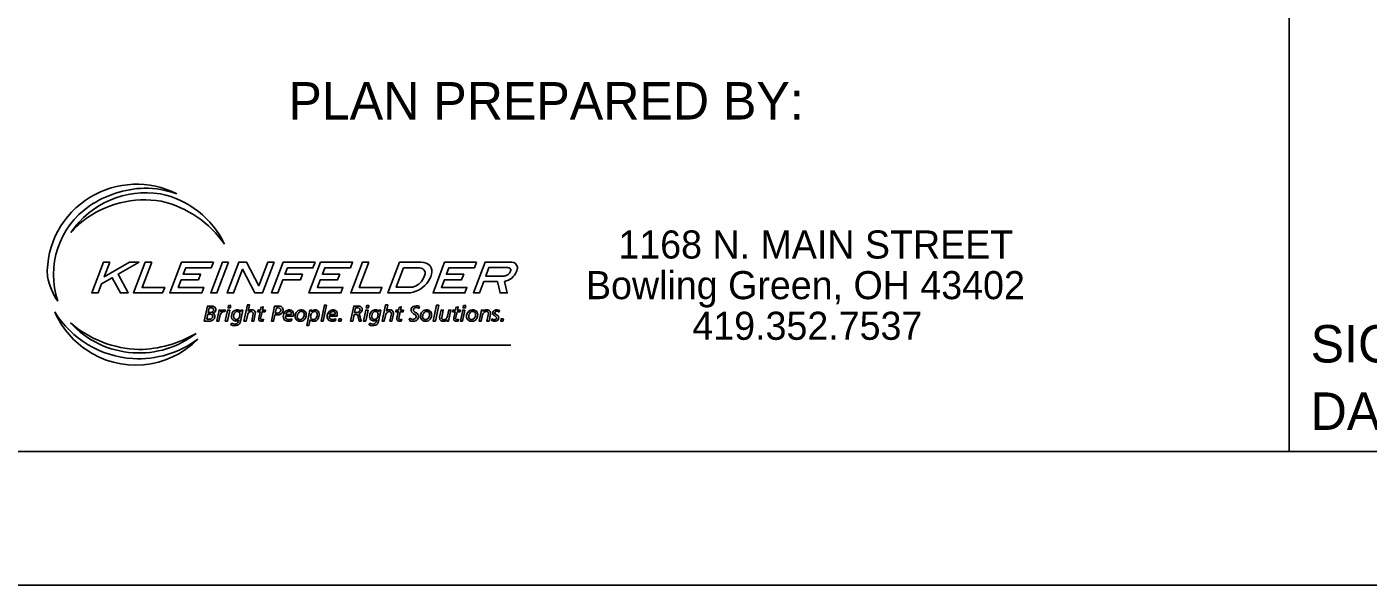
# Model space of a CAD drawing. Extents: x -107 to 120, y -81 to 213.
# Drawn here: x 6.52 to 11.53, y 1.57 to 3.66 of the extents above; entities that cross this region are included whole.
import ezdxf

# ---------------------------------------------------------------- set-up
doc = ezdxf.new("R2010")
doc.units = 0
for name, color, linetype in [('SH_Border', 7, 'Continuous'), ('SH_Cut_Line', 7, 'Continuous'), ('SH_Data', 7, 'Continuous'), ('SH_Text', 7, 'Continuous')]:
    doc.layers.add(name, color=color, linetype=linetype)

msp = doc.modelspace()

# ---------------------------------------------------------------- linework, layer by layer
at = {"layer": 'SH_Border'}
msp.add_lwpolyline([(5.389, 23.0682), (37.389, 23.0682), (37.389, 2.0682), (5.389, 2.0682)], close=True, dxfattribs=at)
at = {"layer": 'SH_Cut_Line'}
msp.add_lwpolyline([(3.889, 1.5682), (37.889, 1.5682), (37.889, 23.5682), (3.889, 23.5682)], close=True, dxfattribs=at)
at = {"layer": 'SH_Data'}
msp.add_line((11.239, 2.0682), (11.239, 5.3182), dxfattribs=at)
at = {"layer": 'SH_Text'}
for p, q in [((8.2506, 2.7552), (8.3209, 2.7553)), ((7.9891, 2.6024), (7.9914, 2.6098)), ((7.2066, 2.5621), (7.1966, 2.5621)), ((7.2109, 2.5874), (7.2019, 2.5874)), ((7.3223, 2.5538), (7.3313, 2.5968)), ((7.4071, 2.5556), (7.4086, 2.5624)), ((7.4511, 2.5783), (7.4613, 2.5783)), ((7.4599, 2.5851), (7.4525, 2.5851)), ((7.5122, 2.5802), (7.4918, 2.5802)), ((7.5132, 2.5565), (7.5146, 2.5636)), ((7.6759, 2.5802), (7.6554, 2.5802)), ((7.6769, 2.5565), (7.6782, 2.5636)), ((7.7589, 2.5876), (7.7488, 2.5876)), ((7.8382, 2.5538), (7.8472, 2.5968)), ((7.923, 2.5556), (7.9245, 2.5624)), ((7.9547, 2.5661), (7.9522, 2.5583)), ((8.1261, 2.5648), (8.1315, 2.5903)), ((8.1353, 2.5556), (8.1368, 2.5624)), ((8.2612, 2.5635), (8.2598, 2.5571)), ((8.2883, 2.5886), (8.2903, 2.5952)), ((7.2887, 2.5481), (7.2867, 2.5411)), ((7.8046, 2.5481), (7.8026, 2.5411))]:
    msp.add_line(p, q, dxfattribs=at)
for points in [[(6.9446, 2.7755), (6.9085, 2.7755), (6.8141, 2.7213), (6.8346, 2.7755), (6.8107, 2.7755), (6.7672, 2.6606), (6.7911, 2.6606), (6.8041, 2.6948), (6.8438, 2.7176), (6.874, 2.6606), (6.9027, 2.6606), (6.8657, 2.7302), (6.9446, 2.7755)], [(6.9909, 2.7755), (6.9668, 2.7755), (6.9233, 2.6606), (7.0319, 2.6606), (7.0399, 2.6811), (6.9552, 2.6811), (6.9909, 2.7755)], [(7.2212, 2.7755), (7.1022, 2.7755), (7.0587, 2.6606), (7.1777, 2.6606), (7.1856, 2.6813), (7.0902, 2.6813), (7.1011, 2.71), (7.1656, 2.71), (7.1735, 2.7307), (7.1089, 2.7307), (7.1179, 2.7545), (7.2133, 2.7545), (7.2212, 2.7755)], [(7.2782, 2.7755), (7.2552, 2.7755), (7.2118, 2.6606), (7.2347, 2.6606), (7.2782, 2.7755)], [(7.3446, 2.7755), (7.3163, 2.7755), (7.2728, 2.6606), (7.2965, 2.6606), (7.33, 2.749), (7.3765, 2.6606), (7.4047, 2.6606), (7.4482, 2.7755), (7.4242, 2.7755), (7.3909, 2.6876), (7.3446, 2.7755)], [(7.5539, 2.7307), (7.4888, 2.7307), (7.4977, 2.7543), (7.5933, 2.7543), (7.6014, 2.7755), (7.4825, 2.7755), (7.439, 2.6606), (7.4623, 2.6606), (7.4809, 2.7099), (7.5461, 2.7099), (7.5539, 2.7307)], [(7.6931, 2.7307), (7.6286, 2.7307), (7.6376, 2.7545), (7.7329, 2.7545), (7.7409, 2.7755), (7.6219, 2.7755), (7.5784, 2.6606), (7.6974, 2.6606), (7.7052, 2.6813), (7.6099, 2.6813), (7.6207, 2.71), (7.6853, 2.71), (7.6931, 2.7307)], [(7.802, 2.7755), (7.7778, 2.7755), (7.7343, 2.6606), (7.843, 2.6606), (7.851, 2.6811), (7.7662, 2.6811), (7.802, 2.7755)], [(7.9978, 2.7755), (7.9168, 2.7755), (7.8733, 2.6606), (7.9465, 2.6606)], [(8.204, 2.7755), (8.085, 2.7755), (8.0415, 2.6606), (8.1605, 2.6606), (8.1684, 2.6813), (8.073, 2.6813), (8.0839, 2.71), (8.1484, 2.71), (8.1563, 2.7307), (8.0917, 2.7307), (8.1007, 2.7545), (8.1961, 2.7545), (8.204, 2.7755)], [(8.336, 2.7755), (8.2363, 2.7755), (8.1928, 2.6606), (8.2148, 2.6606), (8.2308, 2.7029), (8.282, 2.7029), (8.2921, 2.6606), (8.3185, 2.6606), (8.3088, 2.7039)], [(8.3068, 2.7237), (8.2387, 2.7237), (8.2506, 2.7552)], [(7.9556, 2.6817), (7.9042, 2.6817), (7.9317, 2.7544), (7.9918, 2.7544)], [(7.2171, 2.6115), (7.1988, 2.6115), (7.187, 2.5556), (7.21, 2.5556)], [(7.2019, 2.5874), (7.2057, 2.605), (7.2137, 2.605)], [(7.2864, 2.6132), (7.2782, 2.6132), (7.2763, 2.6046), (7.2845, 2.6046), (7.2864, 2.6132)], [(7.3515, 2.5919), (7.3566, 2.6156), (7.3484, 2.6156), (7.3356, 2.5556), (7.3438, 2.5556), (7.3483, 2.5767)], [(7.4159, 2.5968), (7.4047, 2.5968), (7.4072, 2.6088), (7.399, 2.6056), (7.3971, 2.5968), (7.388, 2.5968), (7.3867, 2.5903), (7.3957, 2.5903), (7.3908, 2.5657)], [(7.4675, 2.6115), (7.4499, 2.6115), (7.4381, 2.5556), (7.4463, 2.5556), (7.4511, 2.5783)], [(7.6443, 2.6154), (7.6361, 2.6154), (7.6236, 2.5556), (7.6318, 2.5556), (7.6443, 2.6154)], [(7.7652, 2.6115), (7.7456, 2.6115), (7.7338, 2.5556), (7.742, 2.5556), (7.7473, 2.5806), (7.7544, 2.5806)], [(7.8023, 2.6132), (7.7941, 2.6132), (7.7922, 2.6046), (7.8004, 2.6046), (7.8023, 2.6132)], [(7.8674, 2.5919), (7.8725, 2.6156), (7.8643, 2.6156), (7.8515, 2.5556), (7.8597, 2.5556), (7.8642, 2.5767)], [(7.9318, 2.5968), (7.9206, 2.5968), (7.9231, 2.6088), (7.9149, 2.6056), (7.913, 2.5968), (7.9039, 2.5968), (7.9026, 2.5903), (7.9116, 2.5903), (7.9067, 2.5657)], [(8.0629, 2.6154), (8.0546, 2.6154), (8.0421, 2.5556), (8.0503, 2.5556), (8.0629, 2.6154)], [(8.1315, 2.5903), (8.1427, 2.5903), (8.144, 2.5968), (8.1328, 2.5968), (8.1354, 2.6088), (8.1271, 2.6056), (8.1253, 2.5968), (8.1162, 2.5968), (8.1148, 2.5903), (8.1239, 2.5903), (8.119, 2.5657)], [(8.164, 2.6132), (8.1558, 2.6132), (8.154, 2.6046), (8.1622, 2.6046), (8.164, 2.6132)], [(7.1966, 2.5621), (7.2006, 2.581), (7.2093, 2.581)], [(7.2494, 2.5905), (7.2507, 2.5968), (7.2428, 2.5968), (7.2341, 2.5556), (7.2419, 2.5556), (7.247, 2.5792)], [(7.2643, 2.5904), (7.2659, 2.5968), (7.2589, 2.5968)], [(7.2829, 2.5968), (7.2747, 2.5968), (7.2659, 2.5556), (7.2742, 2.5556), (7.2829, 2.5968)], [(7.3313, 2.5968), (7.3239, 2.5968), (7.3225, 2.5901)], [(7.3701, 2.5821), (7.3646, 2.5556), (7.3723, 2.5556), (7.3779, 2.5821)], [(7.3979, 2.5648), (7.4033, 2.5903), (7.4145, 2.5903), (7.4159, 2.5968)], [(7.4525, 2.5851), (7.4566, 2.6045), (7.4638, 2.6045)], [(7.4905, 2.5701), (7.4908, 2.5742), (7.5196, 2.5742), (7.5202, 2.577)], [(7.5876, 2.5905), (7.5887, 2.5968), (7.582, 2.5968), (7.5698, 2.5394), (7.578, 2.5394), (7.5827, 2.5614)], [(7.6541, 2.5701), (7.6544, 2.5742), (7.6832, 2.5742), (7.6838, 2.577)], [(7.6993, 2.5642), (7.6911, 2.5642), (7.6892, 2.5556), (7.6975, 2.5556), (7.6993, 2.5642)], [(7.7488, 2.5876), (7.7524, 2.6046), (7.761, 2.6046)], [(7.7602, 2.5764), (7.7652, 2.5556), (7.7736, 2.5556), (7.767, 2.5793)], [(7.7988, 2.5968), (7.7906, 2.5968), (7.7818, 2.5556), (7.7901, 2.5556), (7.7988, 2.5968)], [(7.8472, 2.5968), (7.8398, 2.5968), (7.8384, 2.5901)], [(7.886, 2.5821), (7.8805, 2.5556), (7.8882, 2.5556), (7.8938, 2.5821)], [(7.9138, 2.5648), (7.9192, 2.5903), (7.9304, 2.5903), (7.9318, 2.5968)], [(8.0739, 2.5688), (8.0798, 2.5968), (8.0716, 2.5968), (8.0663, 2.5716)], [(8.0937, 2.5616), (8.0926, 2.5556), (8.0999, 2.5556), (8.1087, 2.5968), (8.1005, 2.5968), (8.0955, 2.5733)], [(8.1605, 2.5968), (8.1523, 2.5968), (8.1436, 2.5556), (8.1518, 2.5556), (8.1605, 2.5968)], [(8.2286, 2.5908), (8.2298, 2.5968), (8.2224, 2.5968), (8.2137, 2.5556), (8.2219, 2.5556), (8.2268, 2.5791)], [(8.2484, 2.5836), (8.2425, 2.5556), (8.2507, 2.5556), (8.2561, 2.5808)], [(8.3044, 2.5642), (8.2962, 2.5642), (8.2944, 2.5556), (8.3026, 2.5556), (8.3044, 2.5642)], [(8.3326, 2.4657), (7.3164, 2.4657)]]:
    msp.add_lwpolyline(points, dxfattribs=at)
for centre, radius, start, end in [((6.9345, 2.7342), 0.3328, 63.0899, 121.3353), ((6.931, 2.7354), 0.3299, 120.9374, 182.3516), ((6.9691, 2.6985), 0.3369, 80.6744, 146.0558), ((6.9642, 2.6353), 0.3734, 80.3407, 127.7725), ((6.9778, 2.6584), 0.3942, 92.1375, 123.7556), ((6.9625, 2.6895), 0.3628, 70.2384, 89.8908), ((6.9553, 2.6981), 0.3398, 25.1143, 78.3777), ((6.937, 2.7291), 0.3127, 124.7279, 198.5434), ((6.9379, 2.6194), 0.3942, 34.4536, 76.9641), ((6.9248, 2.6861), 0.3091, 127.7725, 139.547), ((7.9973, 2.7274), 0.0481, 45.8191, 89.4263), ((8.0018, 2.7409), 0.0358, 343.1779, 35.9306), ((8.3215, 2.7436), 0.0116, 30.9282, 92.8587), ((8.3343, 2.752), 0.0235, 15.8602, 85.9527), ((8.3211, 2.7563), 0.0359, 333.9111, 3.4134), ((6.8465, 2.7714), 0.25, 191.4129, 214.5262), ((7.9503, 2.7431), 0.0624, 294.8644, 346.4065), ((7.948, 2.7535), 0.0911, 295.2799, 345.3517), ((7.9919, 2.734), 0.0203, 22.5545, 90.292), ((7.9929, 2.7347), 0.0192, 340.7496, 21.8258), ((8.3052, 2.7515), 0.0278, 273.188, 339.9483), ((8.2984, 2.762), 0.059, 280.1322, 338.6534), ((8.3193, 2.746), 0.0128, 341.295, 16.2465), ((7.9458, 2.7457), 0.0851, 270.5101, 298.8607), ((7.9564, 2.7275), 0.0458, 268.9317, 296.1463), ((7.2142, 2.5966), 0.00845, 14.5669, 93.2204), ((7.2164, 2.5967), 0.0148, 28.8217, 87.6001), ((7.4669, 2.5957), 0.0158, 36.8786, 87.6793), ((7.4634, 2.5965), 0.0183, 337.3357, 28.1453), ((7.7638, 2.5973), 0.0143, 24.3537, 84.3612), ((7.9751, 2.5961), 0.0157, 117.7495, 163.8409), ((7.9808, 2.5765), 0.0359, 92.7278, 111.3007), ((7.979, 2.5934), 0.0124, 85.3728, 140.5265), ((7.9803, 2.5878), 0.0246, 63.0923, 92.7278), ((7.98, 2.5913), 0.0144, 50.4782, 89.939), ((6.933, 2.7216), 0.3314, 203.3176, 235.0704), ((6.944, 2.7846), 0.3703, 211.6203, 266.4398), ((6.933, 2.7216), 0.3314, 203.3176, 235.0704), ((6.944, 2.7846), 0.3703, 211.6203, 266.4398), ((7.2062, 2.5756), 0.0135, 271.8674, 330.8259), ((7.211, 2.573), 0.00818, 23.2405, 101.7775), ((7.2082, 2.5763), 0.0207, 274.8421, 325.7541), ((7.2099, 2.6028), 0.0155, 273.7446, 308.6277), ((7.2112, 2.5731), 0.00788, 328.3862, 23.2405), ((7.2157, 2.6042), 0.0195, 278.6642, 301.5112), ((7.2144, 2.5727), 0.0129, 9.5096, 70.7154), ((7.2141, 2.5971), 0.0084, 310.2808, 10.5581), ((7.2144, 2.5718), 0.0131, 326.795, 13.6323), ((7.2138, 2.5987), 0.0165, 317.423, 18.0377), ((7.2653, 2.5728), 0.0194, 115.713, 160.7037), ((7.2609, 2.5833), 0.0136, 98.2387, 147.9511), ((7.2607, 2.5811), 0.00995, 68.8231, 112.4085), ((7.3156, 2.5736), 0.0268, 153.1201, 200.541), ((7.3046, 2.5715), 0.0158, 207.2493, 259.812), ((7.3096, 2.5781), 0.0195, 76.4234, 156.8498), ((7.3198, 2.573), 0.0229, 134.9845, 190.2941), ((7.3059, 2.5704), 0.00874, 190.0175, 280.7991), ((7.3052, 2.5708), 0.0154, 257.3096, 315.7047), ((7.3103, 2.5814), 0.0102, 66.145, 130.58), ((7.3065, 2.5742), 0.0125, 274.6127, 341.2311), ((7.2981, 2.5606), 0.0181, 322.9431, 358.3704), ((7.312, 2.5859), 0.0113, 21.6426, 78.888), ((7.3097, 2.5814), 0.0105, 3.2154, 63.4686), ((7.2978, 2.5796), 0.0226, 335.4895, 6.081), ((7.3682, 2.573), 0.0202, 120.678, 169.5619), ((7.3622, 2.5847), 0.0129, 95.2859, 145.9293), ((7.362, 2.5834), 0.00818, 46.5529, 120.7681), ((7.3639, 2.5808), 0.017, 55.2436, 99.7855), ((7.3628, 2.5836), 0.00748, 348.1668, 49.4713), ((7.364, 2.5843), 0.0141, 350.6828, 47.5266), ((7.3996, 2.564), 0.00899, 168.837, 239.2244), ((7.4022, 2.5757), 0.0207, 249.7319, 283.8876), ((7.4019, 2.5645), 0.00406, 175.2766, 269.8271), ((7.4019, 2.5724), 0.012, 269.8271, 303.4272), ((7.4605, 2.5995), 0.0145, 267.8598, 317.6882), ((7.4627, 2.5974), 0.0192, 265.6807, 335.6249), ((7.4645, 2.5952), 0.00934, 33.5007, 94.662), ((7.4612, 2.5962), 0.0119, 327.2999, 20.5503), ((7.5034, 2.5728), 0.0209, 165.6438, 220.1539), ((7.506, 2.5743), 0.0231, 116.9109, 170.8013), ((7.4998, 2.574), 0.0192, 229.8498, 272.5151), ((7.5025, 2.572), 0.0122, 188.9982, 224.1507), ((7.505, 2.5779), 0.0135, 113.2444, 170.0416), ((7.5034, 2.5795), 0.0187, 238.9592, 278.5627), ((7.5053, 2.5746), 0.0226, 79.5031, 115.801), ((7.505, 2.5796), 0.0119, 78.1247, 116.2564), ((7.5009, 2.6019), 0.047, 269.6882, 285.2269), ((7.4995, 2.5978), 0.0374, 280.3368, 293.7103), ((7.5043, 2.5832), 0.00858, 27.3851, 68.6637), ((7.5074, 2.5846), 0.0124, 22.1338, 80.4587), ((7.5006, 2.5832), 0.012, 345.5066, 19.4211), ((7.4948, 2.5806), 0.0257, 351.9878, 19.8531), ((7.5492, 2.5751), 0.0225, 144.7204, 185.0527), ((7.5432, 2.5713), 0.0164, 173.7465, 225.576), ((7.5488, 2.5755), 0.0218, 93.0085, 145.1138), ((7.5444, 2.5739), 0.0192, 228.3025, 279.3316), ((7.5469, 2.5721), 0.0124, 171.6619, 234.7522), ((7.5558, 2.5731), 0.0212, 132.6118, 177.8201), ((7.5451, 2.5729), 0.0122, 243.802, 296.7946), ((7.5493, 2.5802), 0.0115, 88.7964, 132.8298), ((7.5478, 2.573), 0.0181, 269.1065, 324.0048), ((7.5499, 2.5768), 0.0207, 44.8616, 96.3333), ((7.5501, 2.5819), 0.00982, 24.8029, 93.3912), ((7.5403, 2.5793), 0.0201, 300.777, 345.0314), ((7.5429, 2.579), 0.0176, 343.9781, 23.6531), ((7.5461, 2.5766), 0.0217, 318.9189, 356.1506), ((7.5444, 2.5791), 0.0236, 350.4774, 31.3769), ((7.5968, 2.5731), 0.0184, 219.5558, 287.4679), ((7.6012, 2.5729), 0.0167, 157.995, 201.3144), ((7.5959, 2.5718), 0.0114, 205.6576, 253.4617), ((7.6033, 2.5745), 0.0182, 120.6491, 165.0946), ((7.6018, 2.5797), 0.0179, 96.9887, 142.7091), ((7.595, 2.5707), 0.0101, 256.7314, 318.3063), ((7.5993, 2.5829), 0.00899, 41.5529, 125.9721), ((7.6015, 2.5815), 0.016, 38.4644, 96.7325), ((7.5931, 2.5765), 0.0228, 293.9558, 350.548), ((7.5885, 2.5791), 0.0207, 313.01, 354.1033), ((7.5961, 2.58), 0.0133, 346.6402, 41.7242), ((7.5898, 2.58), 0.0268, 344.1204, 25.3732), ((7.6671, 2.5728), 0.0209, 165.6438, 220.1539), ((7.6696, 2.5743), 0.0231, 116.9109, 170.8013), ((7.6634, 2.574), 0.0192, 229.8498, 272.5151), ((7.6662, 2.572), 0.0122, 188.9982, 224.1507), ((7.6687, 2.5779), 0.0135, 113.2444, 170.0416), ((7.6671, 2.5795), 0.0187, 238.9592, 278.5627), ((7.669, 2.5746), 0.0226, 79.5031, 115.801), ((7.6686, 2.5796), 0.0119, 78.1247, 116.2564), ((7.6645, 2.6019), 0.047, 269.6882, 285.2269), ((7.6632, 2.5978), 0.0374, 280.3368, 293.7103), ((7.668, 2.5832), 0.00858, 27.3851, 68.6637), ((7.6711, 2.5846), 0.0124, 22.1338, 80.4587), ((7.6643, 2.5832), 0.012, 345.5066, 19.4211), ((7.6584, 2.5806), 0.0257, 351.9878, 19.8531), ((7.755, 2.5752), 0.00539, 12.6271, 95.8955), ((7.7583, 2.5989), 0.0113, 272.8048, 333.3705), ((7.761, 2.5954), 0.00918, 36.0182, 90.1757), ((7.7591, 2.6001), 0.0187, 286.6516, 324.9416), ((7.7617, 2.5772), 0.00573, 22.0732, 62.0788), ((7.7579, 2.5973), 0.0111, 341.543, 18.457), ((7.7611, 2.5989), 0.0163, 324.324, 15.2141), ((7.8315, 2.5736), 0.0268, 153.1201, 200.541), ((7.8205, 2.5715), 0.0158, 207.2493, 259.812), ((7.8255, 2.5781), 0.0195, 76.4234, 156.8498), ((7.8357, 2.573), 0.0229, 134.9845, 190.2941), ((7.8218, 2.5704), 0.00874, 190.0175, 280.7991), ((7.8211, 2.5708), 0.0154, 257.3096, 315.7047), ((7.8262, 2.5814), 0.0102, 66.145, 130.58), ((7.8224, 2.5742), 0.0125, 274.6127, 341.2311), ((7.814, 2.5606), 0.0181, 322.9431, 358.3704), ((7.8279, 2.5859), 0.0113, 21.6426, 78.888), ((7.8256, 2.5814), 0.0105, 3.2154, 63.4686), ((7.8137, 2.5796), 0.0226, 335.4895, 6.081), ((7.8841, 2.573), 0.0202, 120.678, 169.5619), ((7.8781, 2.5847), 0.0129, 95.2859, 145.9293), ((7.8779, 2.5834), 0.00818, 46.5529, 120.7681), ((7.8798, 2.5808), 0.017, 55.2436, 99.7855), ((7.8787, 2.5836), 0.00748, 348.1668, 49.4713), ((7.8799, 2.5843), 0.0141, 350.6828, 47.5266), ((7.9155, 2.564), 0.00899, 168.837, 239.2244), ((7.9181, 2.5757), 0.0207, 249.7319, 283.8876), ((7.9178, 2.5645), 0.00406, 175.2766, 269.8271), ((7.9178, 2.5724), 0.012, 269.8271, 303.4272), ((7.9672, 2.5873), 0.0327, 242.8538, 271.7076), ((7.9668, 2.581), 0.0192, 231.116, 280.1848), ((7.9754, 2.5968), 0.0158, 166.3758, 204.8902), ((7.981, 2.6031), 0.0238, 213.1236, 247.1341), ((7.9686, 2.5746), 0.0199, 268.5943, 323.7031), ((7.9773, 2.5966), 0.00909, 149.5135, 194.896), ((7.9815, 2.6016), 0.0149, 209.565, 249.2556), ((7.9688, 2.572), 0.0099, 277.9705, 354.8943), ((7.9676, 2.5709), 0.011, 0.8577, 68.2517), ((7.9681, 2.5692), 0.0202, 22.5492, 66.2929), ((7.9693, 2.5722), 0.018, 328.4507, 15.0331), ((8.0174, 2.5751), 0.0225, 144.7204, 185.0527), ((8.0113, 2.5713), 0.0164, 173.7465, 225.576), ((8.017, 2.5755), 0.0218, 93.0085, 145.1138), ((8.0126, 2.5739), 0.0192, 228.3025, 279.3316), ((8.0151, 2.5721), 0.0124, 171.6619, 234.7522), ((8.0239, 2.5731), 0.0212, 132.6118, 177.8201), ((8.0133, 2.5729), 0.0122, 243.802, 296.7946), ((8.0174, 2.5802), 0.0115, 88.7964, 132.8298), ((8.016, 2.573), 0.0181, 269.1065, 324.0048), ((8.0181, 2.5768), 0.0207, 44.8616, 96.3333), ((8.0183, 2.5819), 0.00982, 24.8029, 93.3912), ((8.0085, 2.5793), 0.0201, 300.777, 345.0314), ((8.011, 2.579), 0.0176, 343.9781, 23.6531), ((8.0143, 2.5766), 0.0217, 318.9189, 356.1506), ((8.0126, 2.5791), 0.0236, 350.4774, 31.3769), ((8.0817, 2.5684), 0.0157, 168.3727, 218.7252), ((8.0793, 2.569), 0.0143, 226.2913, 272.0825), ((8.0813, 2.5678), 0.00751, 172.4034, 246.5016), ((8.0812, 2.5712), 0.0107, 254.3628, 307.5642), ((8.0807, 2.5704), 0.0157, 266.9051, 326.2062), ((8.0771, 2.5786), 0.0192, 304.0093, 343.9548), ((8.1278, 2.564), 0.00899, 168.837, 239.2244), ((8.1303, 2.5757), 0.0207, 249.7319, 283.8876), ((8.1301, 2.5645), 0.00406, 175.2766, 269.8271), ((8.1301, 2.5724), 0.012, 269.8271, 303.4272), ((8.1835, 2.5713), 0.0164, 173.7465, 225.576), ((8.1895, 2.5751), 0.0225, 144.7204, 185.0527), ((8.1891, 2.5755), 0.0218, 93.0085, 145.1138), ((8.1847, 2.5739), 0.0192, 228.3025, 279.3316), ((8.1872, 2.5721), 0.0124, 171.6619, 234.7522), ((8.1961, 2.5731), 0.0212, 132.6118, 177.8201), ((8.1854, 2.5729), 0.0122, 243.802, 296.7946), ((8.1896, 2.5802), 0.0115, 88.7964, 132.8298), ((8.1881, 2.573), 0.0181, 269.1065, 324.0048), ((8.1902, 2.5768), 0.0207, 44.8616, 96.3333), ((8.1904, 2.5819), 0.00982, 24.8029, 93.3912), ((8.1807, 2.5793), 0.0201, 300.777, 345.0314), ((8.1832, 2.579), 0.0176, 343.9781, 23.6531), ((8.1864, 2.5766), 0.0217, 318.9189, 356.1506), ((8.1847, 2.5791), 0.0236, 350.4774, 31.3769), ((8.2453, 2.5738), 0.0192, 124.0093, 163.9548), ((8.2417, 2.582), 0.0157, 86.9051, 146.2062), ((8.2411, 2.5812), 0.0107, 74.3628, 127.5642), ((8.2431, 2.5834), 0.0143, 46.2913, 92.0825), ((8.241, 2.5846), 0.00751, 352.4034, 66.5016), ((8.2407, 2.5839), 0.0157, 348.3727, 38.7252), ((8.2731, 2.5962), 0.0413, 251.1844, 264.3531), ((8.2701, 2.576), 0.0154, 234.4952, 275.8801), ((8.2744, 2.5855), 0.0096, 162.4577, 215.4949), ((8.275, 2.5855), 0.0102, 115.2791, 163.4117), ((8.2811, 2.5907), 0.018, 216.3564, 239.8219), ((8.2717, 2.5732), 0.0183, 261.4651, 294.96), ((8.2796, 2.581), 0.0164, 82.9331, 122.9177), ((8.2716, 2.5688), 0.0081, 270.828, 326.4407), ((8.2597, 2.5535), 0.0248, 43.1465, 60.3389), ((8.2774, 2.5864), 0.00472, 122.4264, 196.081), ((8.2835, 2.5899), 0.0117, 204.6007, 247.5251), ((8.2805, 2.5816), 0.0105, 41.8722, 123.0859), ((8.2744, 2.5671), 0.00487, 324.9774, 43.6656), ((8.2733, 2.5664), 0.0139, 24.5985, 65.8852), ((8.2726, 2.5708), 0.0157, 295.7964, 327.936), ((8.2805, 2.5735), 0.0237, 65.8068, 87.518), ((8.2739, 2.5674), 0.013, 337.7239, 21.621), ((6.9581, 2.864), 0.4154, 229.4476, 267.9721), ((6.9439, 2.7839), 0.3478, 222.6314, 266.3155), ((6.9438, 2.7836), 0.3475, 266.3155, 307.8631), ((6.9336, 2.8915), 0.4427, 271.2686, 300.3182), ((7.3002, 2.5693), 0.0312, 244.3125, 291.7018), ((7.3006, 2.5635), 0.0194, 232.3021, 281.6769), ((7.3002, 2.5597), 0.0158, 285.8406, 321.2557), ((7.3047, 2.5566), 0.0178, 293.5672, 351.0788), ((7.8161, 2.5693), 0.0312, 244.3125, 291.7018), ((7.8165, 2.5635), 0.0194, 232.3021, 281.6769), ((7.8161, 2.5597), 0.0158, 285.8406, 321.2557), ((7.8206, 2.5566), 0.0178, 293.5672, 351.0788), ((6.9309, 2.7192), 0.3283, 235.1289, 315.2058), ((6.9309, 2.7192), 0.3283, 235.1289, 315.2058), ((6.9406, 2.7904), 0.3759, 267.0055, 306.4292), ((6.9406, 2.7904), 0.3759, 267.0055, 306.4292)]:
    msp.add_arc(centre, radius, start, end, dxfattribs=at)

# ---------------------------------------------------------------- texts
for s, height, p in [('PLAN PREPARED BY:', 0.14, (7.5015, 3.3088)), ('1168 N. MAIN STREET', 0.105, (8.7337, 2.7892)), ('Bowling Green, OH 43402', 0.105, (8.6128, 2.6373)), ('419.352.7537', 0.105, (9.01, 2.4854)), ('SIGNED:', 0.14, (11.319, 2.4006)), ('DATE:', 0.14, (11.319, 2.1487))]:
    msp.add_text(s, height=height, dxfattribs=at).set_placement(p)

doc.saveas('drawing.dxf')
